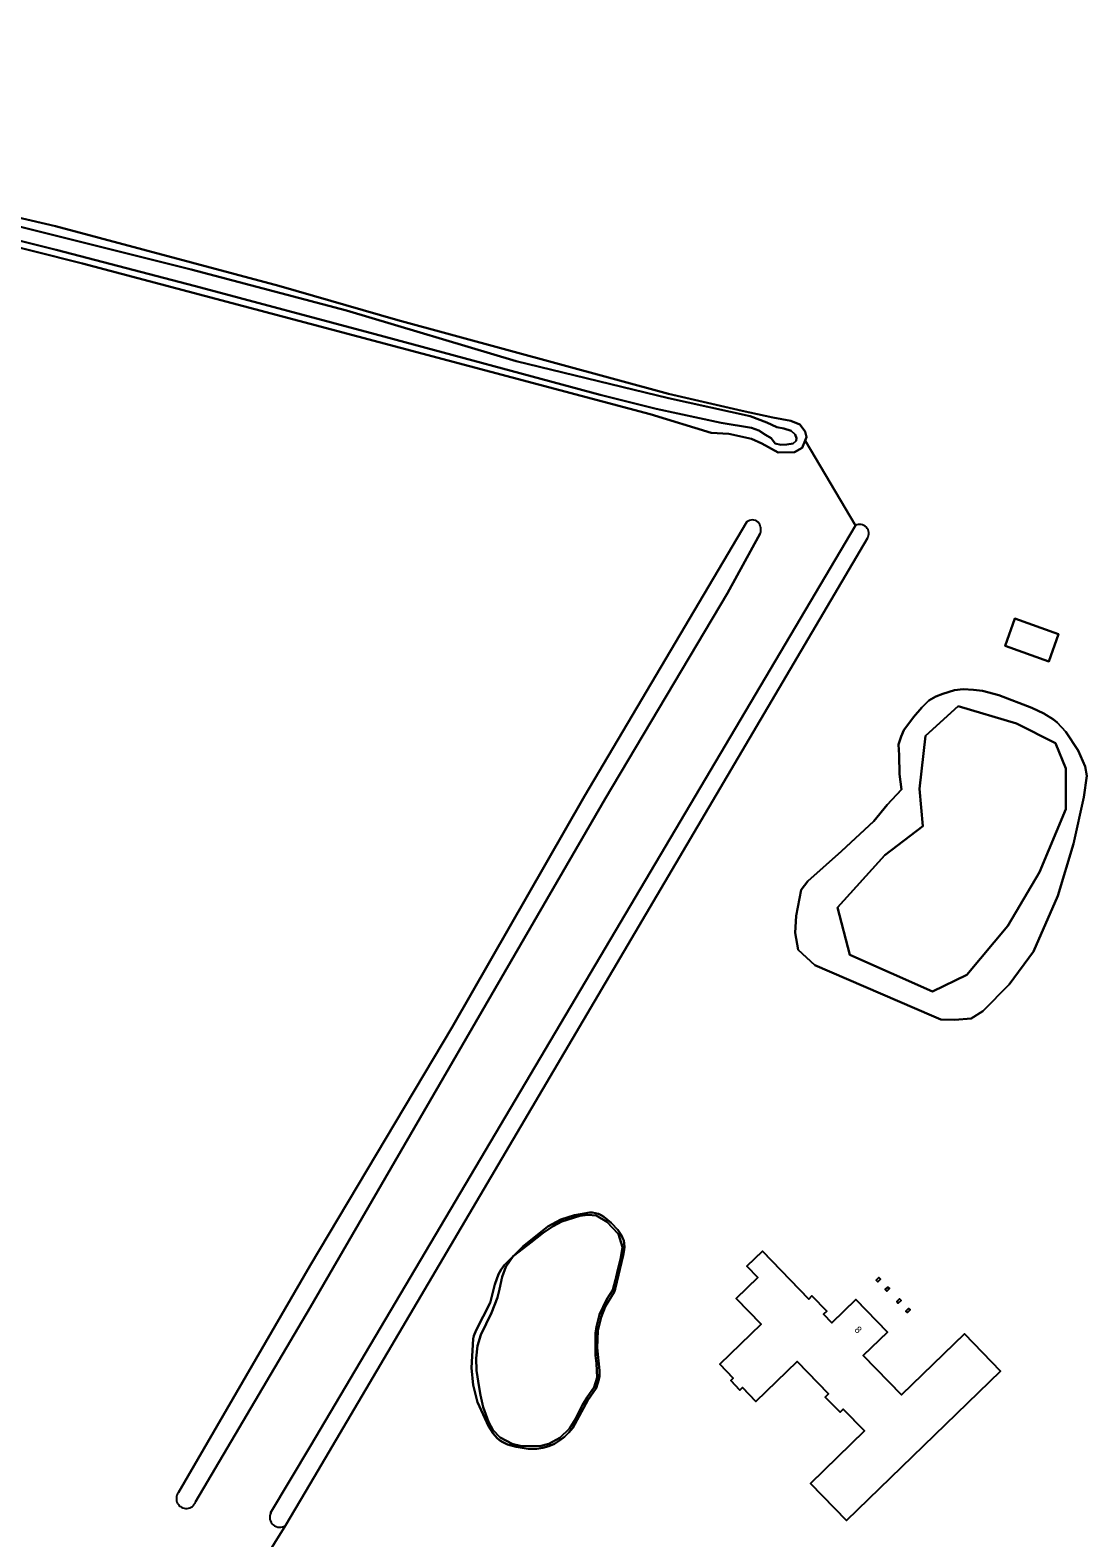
# Model space of a CAD drawing. Extents: x 156502 to 159075, y 384229 to 386100.
# Drawn here: x 158459.7 to 158611.7, y 384547.3 to 384764 of the extents above; entities that cross this region are included whole.
import ezdxf

# ---------------------------------------------------------------- set-up
doc = ezdxf.new("R2010")
doc.units = 0
for name, color, linetype in [('IMGEO_Gemengd_bos', 7, 'Continuous'), ('IMGEO_Greppel_droge_sloot', 7, 'Continuous'), ('IMGEO_Meer_plas_ven_vijver', 7, 'Continuous'), ('IMGEO_Oever', 7, 'Continuous'), ('IMGEO_Pand', 7, 'Continuous'), ('IMGEO_Pand_nummerreeks', 7, 'Continuous'), ('IMGEO_Waterloop', 7, 'Continuous')]:
    doc.layers.add(name, color=color, linetype=linetype)

msp = doc.modelspace()

# ---------------------------------------------------------------- linework, layer by layer
at = {"layer": 'IMGEO_Gemengd_bos'}
for points in [[(158351.99, 384764.03), (158354.67, 384763.47), (158364.64, 384760.87), (158372.91, 384758.88), (158382.72, 384756), (158392.83, 384753.74), (158402.07, 384751.17), (158417.24, 384747.38), (158436.27, 384742.67), (158446.79, 384739.45), (158453.65, 384738.08), (158463.4, 384735.86), (158495.51, 384727.29), (158512.64, 384722.35), (158551.56, 384711.75), (158562.15, 384709.28), (158566.56, 384708.33), (158569.14, 384707.86), (158570.46, 384707.32), (158571.21, 384706.31), (158571.39, 384705.52), (158571.21, 384705.05), (158578.45, 384692.83)], [(158494.33, 384550.86), (158500, 384560.42), (158578.45, 384692.83), (158571.21, 384705.05), (158570.79, 384704), (158569.66, 384703.38), (158567.31, 384703.29), (158564.96, 384704.61), (158563.47, 384705.28), (158560.24, 384705.98), (158557.69, 384706.15), (158548.92, 384708.8), (158500, 384721.83), (158467.26, 384730.47), (158402.28, 384746.84), (158388.89, 384750), (158368.99, 384755.16), (158357.77, 384759.07), (158351.27, 384760.85)], [(158481.06, 384553.77), (158500, 384586.44), (158520.42, 384620.69), (158539.48, 384653.88), (158562.81, 384693.33)], [(158564.76, 384691.66), (158560.03, 384683.09), (158542.46, 384653.53), (158500, 384580.4), (158483.54, 384552.46)], [(158580.17, 384690.99), (158500, 384555.01), (158496.48, 384549.04), (158491.72, 384541.43)], [(158491.72, 384541.43), (158496.48, 384549.04)]]:
    msp.add_lwpolyline(points, dxfattribs=at)
for points in [[(158599.98, 384675.52), (158601.38, 384679.44), (158607.65, 384677.2), (158606.25, 384673.28)], [(158570.64, 384640.41), (158571.57, 384641.69), (158576.41, 384645.97), (158581.08, 384650.29), (158583.01, 384652.67), (158585.04, 384654.85), (158584.76, 384657.08), (158584.71, 384659.8), (158584.65, 384661.32), (158585.01, 384662.48), (158585.4, 384663.41), (158586.77, 384665.26), (158588, 384666.66), (158589, 384667.64), (158589.99, 384668.23), (158591.03, 384668.59), (158592.69, 384669.14), (158593.91, 384669.27), (158595.44, 384669.21), (158596.69, 384669.04), (158599.08, 384668.41), (158603.8, 384666.61), (158605.53, 384665.8), (158606.91, 384664.9), (158607.46, 384664.49), (158608.7, 384663.15), (158610.46, 384660.48), (158611.48, 384658.17), (158611.72, 384656.81), (158611.3, 384653.77), (158609.81, 384647.06), (158607.53, 384639.55), (158604.03, 384631.59), (158600.55, 384626.8), (158596.78, 384622.98), (158595.09, 384621.94), (158592.71, 384621.74), (158590.71, 384621.8), (158589.39, 384622.35), (158572.61, 384629.58), (158570.2, 384631.8), (158569.79, 384634.25), (158569.91, 384636.71)], [(158541.63, 384571.31), (158541.61, 384570.45), (158541.54, 384570.02), (158541.15, 384568.8), (158539.94, 384567.06), (158537.78, 384563.07), (158537.24, 384562.39), (158536.61, 384561.78), (158535.9, 384561.25), (158535.14, 384560.8), (158534.33, 384560.45), (158533.49, 384560.2), (158532.64, 384560.07), (158531.36, 384560.07), (158529.66, 384560.33), (158528.41, 384560.71), (158527.62, 384561.09), (158527.27, 384561.33), (158526.93, 384561.61), (158526.35, 384562.25), (158525.65, 384563.34), (158524.08, 384566.79), (158523.45, 384569.21), (158523.21, 384571.7), (158523.46, 384575.89), (158523.56, 384576.31), (158523.87, 384577.14), (158525.92, 384581.07), (158526.57, 384583.67), (158527.09, 384585.16), (158527.48, 384585.86), (158527.98, 384586.51), (158529.23, 384587.77), (158530.61, 384589.16), (158534.22, 384592.02), (158536.05, 384593.02), (158538.04, 384593.68), (158540.18, 384594.05), (158540.63, 384594.04), (158541.07, 384593.97), (158541.49, 384593.84), (158541.89, 384593.65), (158542.26, 384593.42), (158543.3, 384592.57), (158544.25, 384591.57), (158544.76, 384590.82), (158544.96, 384590.42), (158545.11, 384590), (158545.2, 384589.57), (158545.23, 384589.12), (158545.2, 384588.68), (158545.05, 384587.84), (158543.9, 384583), (158543.72, 384582.59), (158542.44, 384580.48), (158541.85, 384578.99), (158541.41, 384577.01), (158541.27, 384574.6)], [(158594.11, 384576.61), (158599.29, 384571.24), (158577.15, 384549.77), (158571.98, 384555.09), (158579.75, 384562.63), (158576.69, 384565.78), (158576.22, 384565.32), (158574.1, 384567.51), (158574.57, 384567.97), (158570.05, 384572.63), (158564.11, 384566.87), (158562.18, 384568.87), (158561.81, 384568.52), (158560.5, 384569.87), (158560.87, 384570.22), (158558.93, 384572.22), (158564.87, 384577.98), (158561.27, 384581.69), (158564.4, 384584.72), (158562.84, 384586.33), (158565.05, 384588.47), (158571.72, 384581.6), (158572.19, 384582.06), (158574.31, 384579.88), (158573.84, 384579.42), (158575.04, 384578.18), (158578.51, 384581.53), (158583.03, 384576.85), (158579.57, 384573.5), (158585.06, 384567.83)], [(158581.8, 384584.7), (158582.04, 384584.47), (158581.66, 384584.09), (158581.42, 384584.32)], [(158583.34, 384583.1), (158582.96, 384582.72), (158582.73, 384582.95), (158583.11, 384583.33)], [(158584.78, 384581.63), (158585, 384581.4), (158584.6, 384581.01), (158584.38, 384581.24)], [(158586.09, 384580.26), (158586.31, 384580.03), (158585.93, 384579.65), (158585.7, 384579.88)]]:
    msp.add_lwpolyline(points, close=True, dxfattribs=at)
for centre, radius, start, end in [((158563.61, 384692.4), 1.22, 47.6185, 130.5392), ((158563.21, 384692.2), 1.64, 340.9187, 42.171), ((158579.05, 384691.67), 1.31, 328.5209, 117.4182), ((158482.19, 384552.91), 1.42, 142.793, 341.4401), ((158495.65, 384550.23), 1.45, 154.4878, 305.0036)]:
    msp.add_arc(centre, radius, start, end, dxfattribs=at)
at = {"layer": 'IMGEO_Greppel_droge_sloot'}
for points in [[(158562.81, 384693.33), (158539.48, 384653.88), (158520.42, 384620.69), (158500, 384586.44), (158481.06, 384553.77)], [(158578.45, 384692.83), (158500, 384560.42), (158494.33, 384550.86)], [(158496.48, 384549.04), (158500, 384555.01), (158580.17, 384690.99)], [(158542.46, 384653.53), (158560.03, 384683.09), (158564.76, 384691.66)], [(158483.54, 384552.46), (158500, 384580.4), (158542.46, 384653.53)]]:
    msp.add_lwpolyline(points, dxfattribs=at)
for centre, radius, start, end in [((158563.61, 384692.4), 1.22, 47.6185, 130.5392), ((158563.21, 384692.2), 1.64, 340.9187, 42.171), ((158579.05, 384691.67), 1.31, 328.5209, 117.4182), ((158482.19, 384552.91), 1.42, 142.793, 341.4401), ((158495.65, 384550.23), 1.45, 154.4878, 305.0036)]:
    msp.add_arc(centre, radius, start, end, dxfattribs=at)
at = {"layer": 'IMGEO_Meer_plas_ven_vijver'}
for points in [[(158593.23, 384666.84), (158588.52, 384662.59), (158587.67, 384654.94), (158588.14, 384649.61), (158582.65, 384645.44), (158575.85, 384637.87), (158577.63, 384631.07), (158589.52, 384625.82), (158594.47, 384628.22), (158600.34, 384635.24), (158604.9, 384642.97), (158608.68, 384652.01), (158608.68, 384657.88), (158607.21, 384661.51), (158601.58, 384664.36)], [(158529.23, 384587.77), (158528.14, 384586.22), (158527.61, 384584.78), (158527.24, 384583.04), (158526.96, 384581.8), (158526.11, 384579.64), (158525.31, 384578.05), (158524.58, 384576.45), (158524.07, 384574.86), (158523.87, 384573.1), (158523.95, 384571.32), (158524.31, 384568.87), (158524.51, 384567.78), (158524.91, 384566.07), (158525.67, 384563.97), (158526.3, 384562.82), (158527.32, 384561.68), (158529.09, 384560.8), (158530.28, 384560.52), (158533.06, 384560.43), (158534.34, 384560.78), (158535.93, 384561.65), (158537.33, 384562.99), (158538.18, 384564.36), (158539.19, 384566.41), (158539.84, 384567.47), (158540.86, 384568.91), (158541.28, 384570.3), (158541.21, 384572.35), (158541.04, 384573.49), (158541.06, 384576.71), (158541.2, 384577.64), (158541.64, 384579.36), (158542.7, 384581.56), (158543.55, 384582.94), (158543.93, 384584.35), (158544.27, 384585.85), (158544.68, 384587.56), (158544.92, 384589.05), (158544.34, 384590.92), (158542.68, 384592.71), (158541.15, 384593.63), (158539.96, 384593.73), (158538.8, 384593.54), (158536.19, 384592.74), (158534.97, 384592.1), (158533.52, 384591.1), (158531.71, 384589.7), (158530.65, 384588.89)]]:
    msp.add_lwpolyline(points, close=True, dxfattribs=at)
at = {"layer": 'IMGEO_Oever'}
for points in [[(158402.28, 384746.84), (158467.26, 384730.47), (158500, 384721.83), (158548.92, 384708.8), (158557.69, 384706.15), (158560.24, 384705.98), (158563.47, 384705.28), (158564.96, 384704.61), (158567.31, 384703.29), (158569.66, 384703.38), (158570.79, 384704), (158571.21, 384705.05), (158571.39, 384705.52), (158571.21, 384706.31), (158570.46, 384707.32), (158569.14, 384707.86), (158566.56, 384708.33), (158562.15, 384709.28), (158551.56, 384711.75), (158512.64, 384722.35), (158495.51, 384727.29), (158463.4, 384735.86), (158453.65, 384738.08)], [(158434.91, 384741.6), (158462.75, 384734.67), (158482.89, 384729.61), (158505.24, 384723.74), (158529.64, 384716.45), (158551.57, 384711.1), (158563.29, 384708.52), (158565.69, 384707.6), (158567.12, 384706.97), (158568.14, 384706.74), (158569.18, 384706.44), (158569.76, 384705.9), (158569.94, 384705.39), (158569.93, 384705.01), (158569.48, 384704.58), (158568.57, 384704.46), (158567.71, 384704.43), (158566.91, 384704.59), (158566.31, 384705.38), (158565.52, 384705.85), (158564.55, 384706.45), (158563.51, 384706.85), (158559.14, 384707.56), (158549.8, 384709.57), (158541.74, 384711.59), (158509.36, 384720.34), (158483.53, 384727.24), (158463.49, 384732.43), (158436.54, 384739.14)]]:
    msp.add_lwpolyline(points, dxfattribs=at)
for points in [[(158600.55, 384626.8), (158604.03, 384631.59), (158607.53, 384639.55), (158609.81, 384647.06), (158611.3, 384653.77), (158611.72, 384656.81), (158611.48, 384658.17), (158610.46, 384660.48), (158608.7, 384663.15), (158607.46, 384664.49), (158606.91, 384664.9), (158605.53, 384665.8), (158603.8, 384666.61), (158599.08, 384668.41), (158596.69, 384669.04), (158595.44, 384669.21), (158593.91, 384669.27), (158592.69, 384669.14), (158591.03, 384668.59), (158589.99, 384668.23), (158589, 384667.64), (158588, 384666.66), (158586.77, 384665.26), (158585.4, 384663.41), (158585.01, 384662.48), (158584.65, 384661.32), (158584.71, 384659.8), (158584.76, 384657.08), (158585.04, 384654.85), (158583.01, 384652.67), (158581.08, 384650.29), (158576.41, 384645.97), (158571.57, 384641.69), (158570.64, 384640.41), (158569.91, 384636.71), (158569.79, 384634.25), (158570.2, 384631.8), (158572.61, 384629.58), (158589.39, 384622.35), (158590.71, 384621.8), (158592.71, 384621.74), (158595.09, 384621.94), (158596.78, 384622.98)], [(158593.23, 384666.84), (158601.58, 384664.36), (158607.21, 384661.51), (158608.68, 384657.88), (158608.68, 384652.01), (158604.9, 384642.97), (158600.34, 384635.24), (158594.47, 384628.22), (158589.52, 384625.82), (158577.63, 384631.07), (158575.85, 384637.87), (158582.65, 384645.44), (158588.14, 384649.61), (158587.67, 384654.94), (158588.52, 384662.59)], [(158529.23, 384587.77), (158527.98, 384586.51), (158527.48, 384585.86), (158527.09, 384585.16), (158526.57, 384583.67), (158525.92, 384581.07), (158523.87, 384577.14), (158523.56, 384576.31), (158523.46, 384575.89), (158523.21, 384571.7), (158523.45, 384569.21), (158524.08, 384566.79), (158525.65, 384563.34), (158526.35, 384562.25), (158526.93, 384561.61), (158527.27, 384561.33), (158527.62, 384561.09), (158528.41, 384560.71), (158529.66, 384560.33), (158531.36, 384560.07), (158532.64, 384560.07), (158533.49, 384560.2), (158534.33, 384560.45), (158535.14, 384560.8), (158535.9, 384561.25), (158536.61, 384561.78), (158537.24, 384562.39), (158537.78, 384563.07), (158539.94, 384567.06), (158541.15, 384568.8), (158541.54, 384570.02), (158541.61, 384570.45), (158541.63, 384571.31), (158541.27, 384574.6), (158541.41, 384577.01), (158541.85, 384578.99), (158542.44, 384580.48), (158543.72, 384582.59), (158543.9, 384583), (158545.05, 384587.84), (158545.2, 384588.68), (158545.23, 384589.12), (158545.2, 384589.57), (158545.11, 384590), (158544.96, 384590.42), (158544.76, 384590.82), (158544.25, 384591.57), (158543.3, 384592.57), (158542.26, 384593.42), (158541.89, 384593.65), (158541.49, 384593.84), (158541.07, 384593.97), (158540.63, 384594.04), (158540.18, 384594.05), (158538.04, 384593.68), (158536.05, 384593.02), (158534.22, 384592.02), (158530.61, 384589.16)], [(158529.23, 384587.77), (158530.65, 384588.89), (158531.71, 384589.7), (158533.52, 384591.1), (158534.97, 384592.1), (158536.19, 384592.74), (158538.8, 384593.54), (158539.96, 384593.73), (158541.15, 384593.63), (158542.68, 384592.71), (158544.34, 384590.92), (158544.92, 384589.05), (158544.68, 384587.56), (158544.27, 384585.85), (158543.93, 384584.35), (158543.55, 384582.94), (158542.7, 384581.56), (158541.64, 384579.36), (158541.2, 384577.64), (158541.06, 384576.71), (158541.04, 384573.49), (158541.21, 384572.35), (158541.28, 384570.3), (158540.86, 384568.91), (158539.84, 384567.47), (158539.19, 384566.41), (158538.18, 384564.36), (158537.33, 384562.99), (158535.93, 384561.65), (158534.34, 384560.78), (158533.06, 384560.43), (158530.28, 384560.52), (158529.09, 384560.8), (158527.32, 384561.68), (158526.3, 384562.82), (158525.67, 384563.97), (158524.91, 384566.07), (158524.51, 384567.78), (158524.31, 384568.87), (158523.95, 384571.32), (158523.87, 384573.1), (158524.07, 384574.86), (158524.58, 384576.45), (158525.31, 384578.05), (158526.11, 384579.64), (158526.96, 384581.8), (158527.24, 384583.04), (158527.61, 384584.78), (158528.14, 384586.22)]]:
    msp.add_lwpolyline(points, close=True, dxfattribs=at)
at = {"layer": 'IMGEO_Pand'}
for points in [[(158601.38, 384679.44), (158599.98, 384675.52), (158606.25, 384673.28), (158607.65, 384677.2)], [(158577.15, 384549.77), (158599.29, 384571.24), (158594.11, 384576.61), (158585.06, 384567.83), (158579.57, 384573.5), (158583.03, 384576.85), (158578.51, 384581.53), (158575.04, 384578.18), (158573.84, 384579.42), (158574.31, 384579.88), (158572.19, 384582.06), (158571.72, 384581.6), (158565.05, 384588.47), (158562.84, 384586.33), (158564.4, 384584.72), (158561.27, 384581.69), (158564.87, 384577.98), (158558.93, 384572.22), (158560.87, 384570.22), (158560.5, 384569.87), (158561.81, 384568.52), (158562.18, 384568.87), (158564.11, 384566.87), (158570.05, 384572.63), (158574.57, 384567.97), (158574.1, 384567.51), (158576.22, 384565.32), (158576.69, 384565.78), (158579.75, 384562.63), (158571.98, 384555.09)], [(158581.66, 384584.09), (158582.04, 384584.47), (158581.8, 384584.7), (158581.42, 384584.32)], [(158582.96, 384582.72), (158583.34, 384583.1), (158583.11, 384583.33), (158582.73, 384582.95)], [(158584.6, 384581.01), (158585, 384581.4), (158584.78, 384581.63), (158584.38, 384581.24)], [(158585.93, 384579.65), (158586.31, 384580.03), (158586.09, 384580.26), (158585.7, 384579.88)]]:
    msp.add_lwpolyline(points, close=True, dxfattribs=at)
at = {"layer": 'IMGEO_Waterloop'}
msp.add_lwpolyline([(158436.54, 384739.14), (158463.49, 384732.43), (158483.53, 384727.24), (158509.36, 384720.34), (158541.74, 384711.59), (158549.8, 384709.57), (158559.14, 384707.56), (158563.51, 384706.85), (158564.55, 384706.45), (158565.52, 384705.85), (158566.31, 384705.38), (158566.91, 384704.59), (158567.71, 384704.43), (158568.57, 384704.46), (158569.48, 384704.58), (158569.93, 384705.01), (158569.94, 384705.39), (158569.76, 384705.9), (158569.18, 384706.44), (158568.14, 384706.74), (158567.12, 384706.97), (158565.69, 384707.6), (158563.29, 384708.52), (158551.57, 384711.1), (158529.64, 384716.45), (158505.24, 384723.74), (158482.89, 384729.61), (158462.75, 384734.67), (158434.91, 384741.6)], dxfattribs=at)

# ---------------------------------------------------------------- texts
at = {"layer": 'IMGEO_Pand_nummerreeks'}
msp.add_text('8', height=1, rotation=314.072, dxfattribs=at).set_placement((158578.22, 384577.1))

doc.saveas('drawing.dxf')
